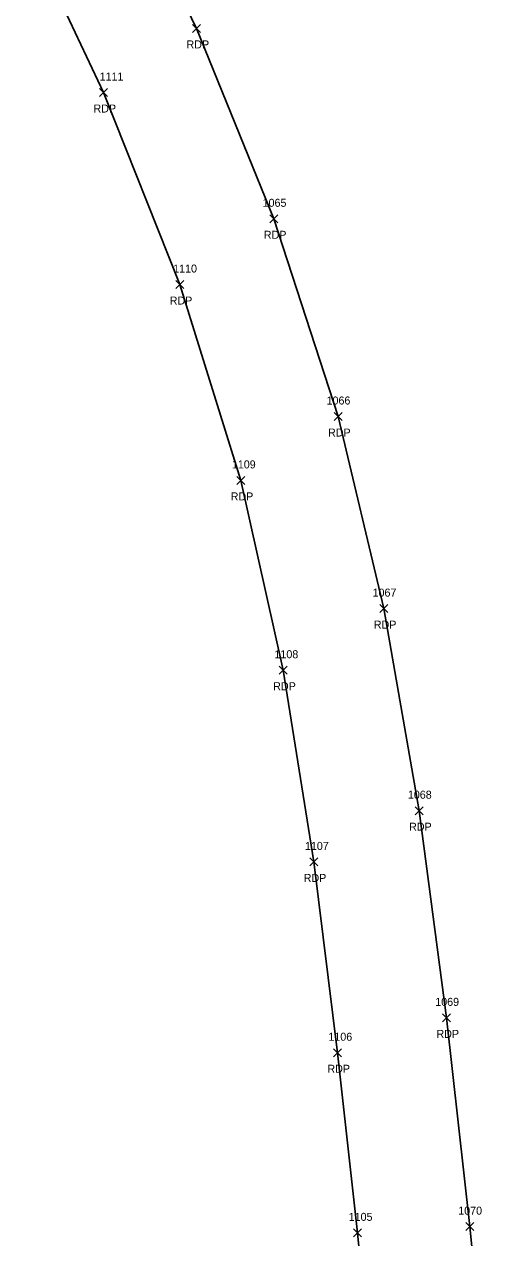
# Model space of a CAD drawing. Extents: x 1503463 to 1505240, y 712171 to 717196.
# Drawn here: x 1505035.7 to 1505151, y 713518.5 to 713821.7 of the extents above; entities that cross this region are included whole.
import ezdxf

# ---------------------------------------------------------------- set-up
doc = ezdxf.new("R2010")
doc.units = 0
for name, color, linetype in [('P_A', 7, 'Continuous'), ('P_I', 7, 'Continuous'), ('P_TIC', 7, 'Continuous'), ('PET', 7, 'Continuous')]:
    doc.layers.add(name, color=color, linetype=linetype)

msp = doc.modelspace()

# ---------------------------------------------------------------- linework, layer by layer
at = {"layer": 'P_TIC'}
for points in [[(1505077.73, 713819.71), (1505079.73, 713821.71)], [(1505079.73, 713819.71), (1505077.73, 713821.71)], [(1505054.48, 713803.69), (1505056.48, 713805.69)], [(1505056.48, 713803.69), (1505054.48, 713805.69)], [(1505097.05, 713772.13), (1505099.05, 713774.13)], [(1505099.05, 713772.13), (1505097.05, 713774.13)], [(1505073.52, 713755.7), (1505075.52, 713757.7)], [(1505075.52, 713755.7), (1505073.52, 713757.7)], [(1505113.09, 713722.72), (1505115.09, 713724.72)], [(1505115.09, 713722.72), (1505113.09, 713724.72)], [(1505088.76, 713706.75), (1505090.76, 713708.75)], [(1505090.76, 713706.75), (1505088.76, 713708.75)], [(1505124.53, 713674.71), (1505126.53, 713676.71)], [(1505126.53, 713674.71), (1505124.53, 713676.71)], [(1505099.39, 713659.31), (1505101.39, 713661.31)], [(1505101.39, 713659.31), (1505099.39, 713661.31)], [(1505133.35, 713624.21), (1505135.35, 713626.21)], [(1505135.35, 713624.21), (1505133.35, 713626.21)], [(1505107.01, 713611.4), (1505109.01, 713613.4)], [(1505109.01, 713611.4), (1505107.01, 713613.4)], [(1505140.19, 713572.44), (1505142.19, 713574.44)], [(1505142.19, 713572.44), (1505140.19, 713574.44)], [(1505112.93, 713563.72), (1505114.93, 713565.72)], [(1505114.93, 713563.72), (1505112.93, 713565.72)], [(1505145.98, 713520.26), (1505147.98, 713522.26)], [(1505147.98, 713520.26), (1505145.98, 713522.26)], [(1505117.94, 713518.71), (1505119.94, 713520.71)], [(1505119.94, 713518.71), (1505117.94, 713520.71)]]:
    msp.add_lwpolyline(points, dxfattribs=at)
at = {"layer": 'PET'}
for points in [[(1505057.05, 713865.49), (1505078.73, 713820.71), (1505098.05, 713773.13), (1505114.09, 713723.72), (1505125.53, 713675.71), (1505134.35, 713625.21), (1505141.19, 713573.44), (1505146.98, 713521.26), (1505150.98, 713481.09)], [(1505123.35, 713474.65), (1505118.94, 713519.71), (1505113.93, 713564.72), (1505108.01, 713612.4), (1505100.39, 713660.31), (1505089.76, 713707.75), (1505074.52, 713756.7), (1505055.48, 713804.69), (1505035.67, 713846.75)]]:
    msp.add_lwpolyline(points, dxfattribs=at)

# ---------------------------------------------------------------- texts
at = {"layer": 'P_A'}
for p in [(1505076.22, 713815.71), (1505052.97, 713799.69), (1505095.54, 713768.13), (1505072.01, 713751.7), (1505111.57, 713718.72), (1505087.25, 713702.75), (1505123.02, 713670.71), (1505097.88, 713655.31), (1505131.84, 713620.21), (1505105.5, 713607.4), (1505138.68, 713568.44), (1505111.42, 713559.72)]:
    msp.add_text('RDP', height=2, dxfattribs=at).set_placement(p)
at = {"layer": 'P_I'}
for s, p in [('1111', (1505054.49, 713807.69)), ('1065', (1505095.23, 713776.13)), ('1110', (1505072.88, 713759.7)), ('1066', (1505111.21, 713726.72)), ('1109', (1505087.55, 713710.75)), ('1067', (1505122.71, 713678.71)), ('1108', (1505098.19, 713663.31)), ('1068', (1505131.53, 713628.21)), ('1107', (1505105.81, 713615.4)), ('1069', (1505138.37, 713576.44)), ('1106', (1505111.67, 713567.72)), ('1105', (1505116.74, 713522.71)), ('1070', (1505144.12, 713524.26))]:
    msp.add_text(s, height=2, dxfattribs=at).set_placement(p)

doc.saveas('drawing.dxf')
